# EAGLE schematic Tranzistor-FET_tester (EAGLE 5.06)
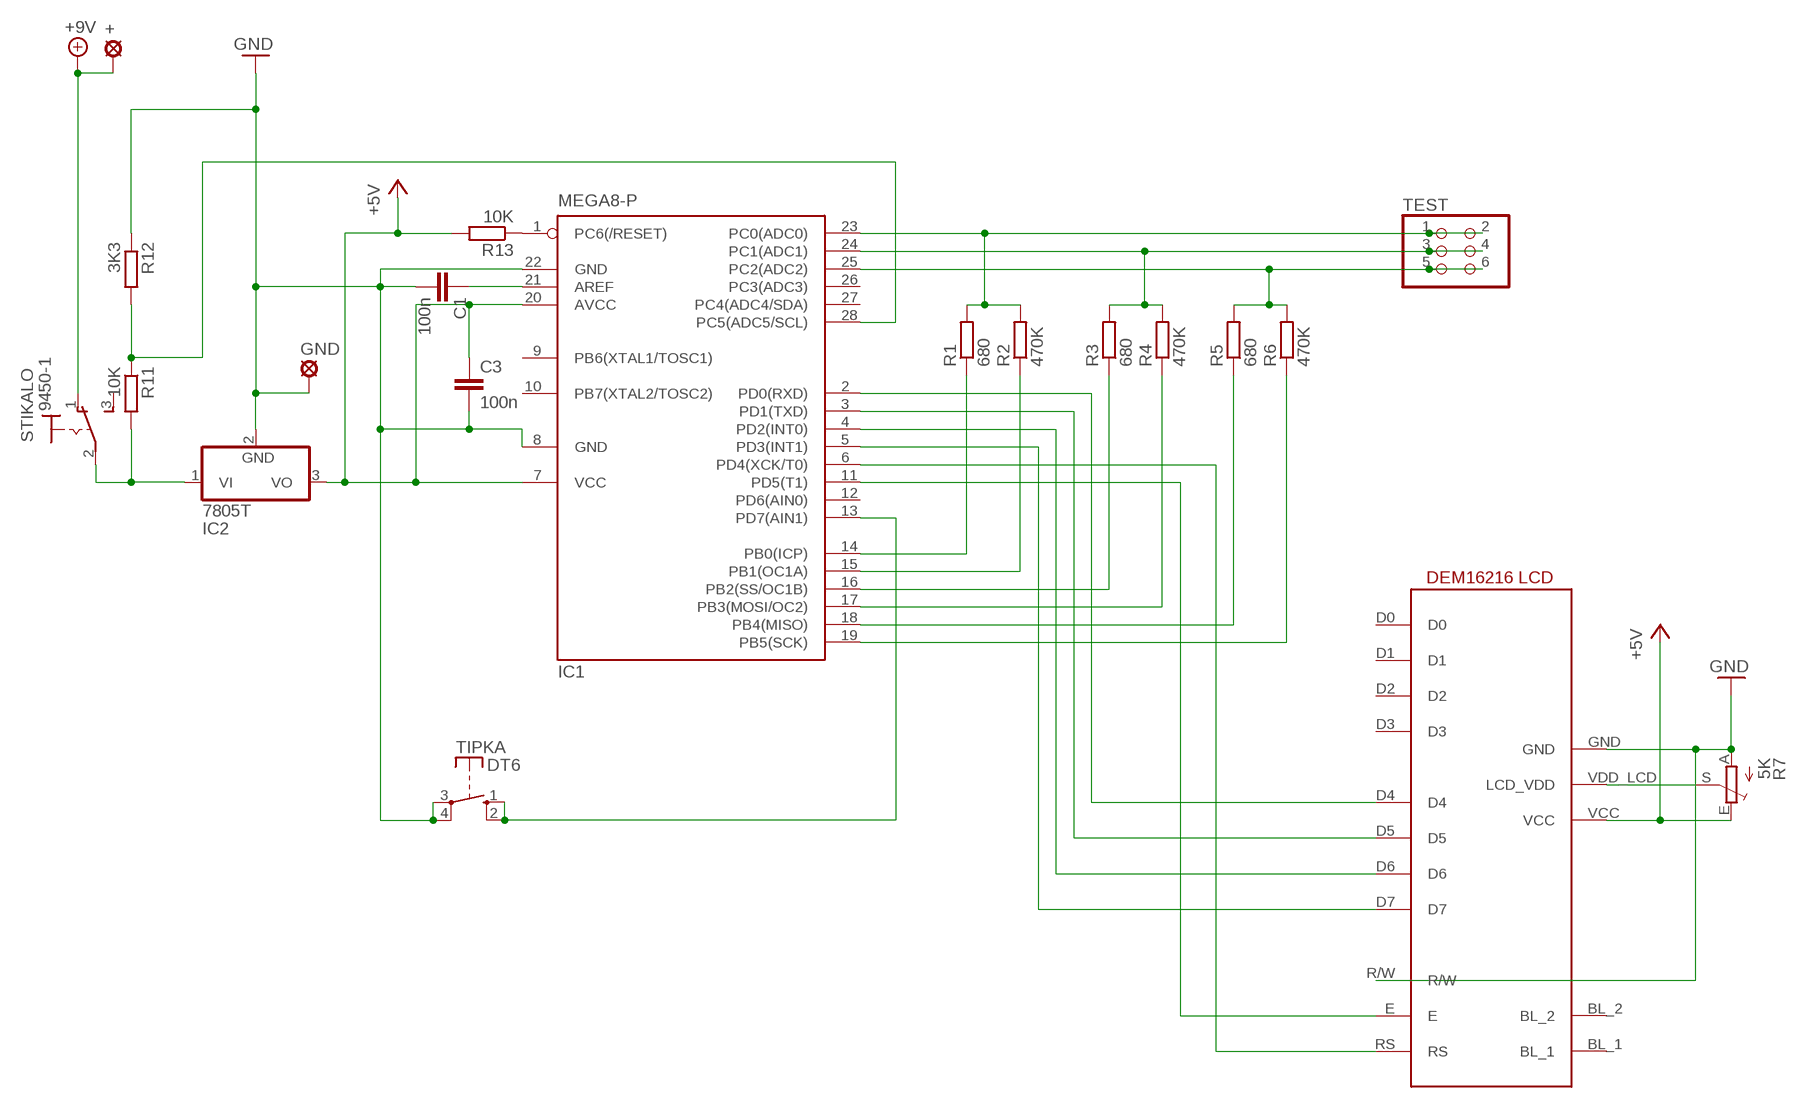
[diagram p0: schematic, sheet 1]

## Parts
+  MCS10B  [MCS10B]
C1  100n  C-EU050-025X075  [C050-025X075]
C3  100n  C-EU050-025X075  [C050-025X075]
GND  MCS10B  [MCS10B]
IC1  MEGA8-P  [DIL28-3]
IC2  7805T  [TO220H]
R1  680  R-EU_0207/12  [0207/12]
R2  470K  R-EU_0207/12  [0207/12]
R3  680  R-EU_0207/12  [0207/12]
R4  470K  R-EU_0207/12  [0207/12]
R5  680  R-EU_0207/12  [0207/12]
R6  470K  R-EU_0207/12  [0207/12]
R7  5K  TRIM_EU-CA6V  [CA6V]
R11  10K  R-EU_0207/12  [0207/12]
R12  3K3  R-EU_0207/12  [0207/12]
R13  10K  R-EU_0207/12  [0207/12]
STIKALO  9450-1  M9040P  [M9040P]
TEST  PINHD-2X3  [2X03]
TIPKA  DT6  [DT6]
U$1  DEM16216  [DEM16216]

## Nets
+5V: C3.1 IC1.7(VCC) IC1.20(AVCC) IC2.3(VO) R7.E R13.2 U$1.VCC
+9V: +.MP STIKALO.1(O)
GND: C1.2 C3.2 GND.MP IC1.8(GND) IC1.22(GND) IC2.2(GND) R7.A R12.1 TIPKA.3(P) TIPKA.4(P) U$1.GND U$1.R/W
N$1: IC1.23(PC0(ADC0)) R1.2 R2.2 TEST.1 TEST.2
N$2: IC1.24(PC1(ADC1)) R3.2 R4.2 TEST.3 TEST.4
N$3: IC1.25(PC2(ADC2)) R5.2 R6.2 TEST.5 TEST.6
N$4: IC1.13(PD7(AIN1)) TIPKA.1(S) TIPKA.2(S)
N$6: R7.S U$1.VDD_LCD(LCD_VDD)
N$7: IC1.28(PC5(ADC5/SCL)) R11.1 R12.2
N$9: IC1.14(PB0(ICP)) R1.1
N$10: IC1.15(PB1(OC1A)) R2.1
N$11: IC1.16(PB2(SS/OC1B)) R3.1
N$12: IC1.17(PB3(MOSI/OC2)) R4.1
N$13: IC1.18(PB4(MISO)) R5.1
N$14: IC1.19(PB5(SCK)) R6.1
N$15: IC1.1(PC6(/RESET)) R13.1
N$17: C1.1 IC1.21(AREF)
N$23: IC2.1(VI) R11.2 STIKALO.2(P)
N$24: IC1.2(PD0(RXD)) U$1.D4
N$25: IC1.3(PD1(TXD)) U$1.D5
N$26: IC1.4(PD2(INT0)) U$1.D6
N$27: IC1.5(PD3(INT1)) U$1.D7
N$28: IC1.6(PD4(XCK/T0)) U$1.RS
N$29: IC1.11(PD5(T1)) U$1.E
Unconnected: IC1.9(PB6(XTAL1/TOSC1)) IC1.10(PB7(XTAL2/TOSC2)) IC1.12(PD6(AIN0)) IC1.26(PC3(ADC3)) IC1.27(PC4(ADC4/SDA)) STIKALO.3(S) U$1.BL_1 U$1.BL_2 U$1.D0 U$1.D1 U$1.D2 U$1.D3

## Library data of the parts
+ GND = solpad:MCS10B: SOLDER PAD
C1 C3 = rcl:C-EU: CAPACITOR, European symbol
IC1 = atmel:MEGA8-P: MICROCONTROLLER 8 Kbytes FLASH, 1 kbytes SRAM, 512 bytes EEPROM, USART, 4-channel 10 bit ADC, 2-channel 8 bit ADC Pin compatible with Atmega48, ATMega88, ATMega168 Source: avr.lbr
IC2 = linear:78*: Positive VOLTAGE REGULATOR Source: http://cache.national.com/ds/LM/LM78L05.pdf http://www.fairchildsemi.com/ds/LM/LM7805.pdf
R1-R6 R11-R13 = rcl:R-EU_: RESISTOR, European symbol
R7 = pot:TRIM_EU-: POTENTIOMETER
STIKALO = switch:M9040P: TOGGLE SWITCH Marquardt
TEST = pinhead:PINHD-2X3: PIN HEADER
TIPKA = switch-misc:DT: ITT SWITCH
U$1 = lcd:DEM16216: DEM16216 2x16 alphabetic LCD module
